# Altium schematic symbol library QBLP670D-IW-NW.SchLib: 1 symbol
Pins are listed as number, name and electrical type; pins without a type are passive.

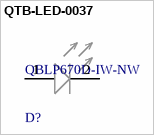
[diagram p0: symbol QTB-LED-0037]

## QTB-LED-0037
designator D?, comment QBLP670D-IW-NW
LED NEUTRAL WHITE CLEAR 2PLCC SMD; Manufacturer: QT Brightek (QTB); Lens Size: 2.4mm; Luminous Intensity: 6800mcd; Test Current: 20mA; Lens Color: Colorless; Lens Style: Round with Domed Top; Forward Voltage: 3.1V; Viewing Angle: 30°
footprint QBLP670D-IW-NW
pins: 1 ANODE (+), 2 CATHODE (-)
